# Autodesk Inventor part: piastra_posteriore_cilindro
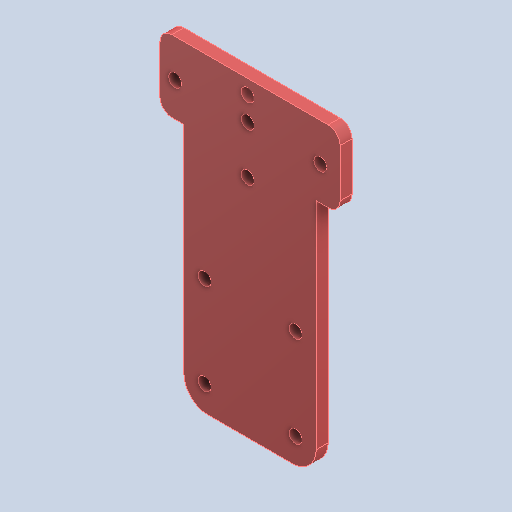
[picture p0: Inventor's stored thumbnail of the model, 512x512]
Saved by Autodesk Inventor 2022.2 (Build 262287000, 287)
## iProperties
Created: 2024-10
Part Number: piastra_posteriore_cilindro
Material: Acciaio inossidabile
Document SubType Name: Modeling
Designer: 18907419
Density: 8 g/cm^3
Appearance: Default
Author: 18907419
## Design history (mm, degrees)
feature "Solido1"
node "Solido2"
